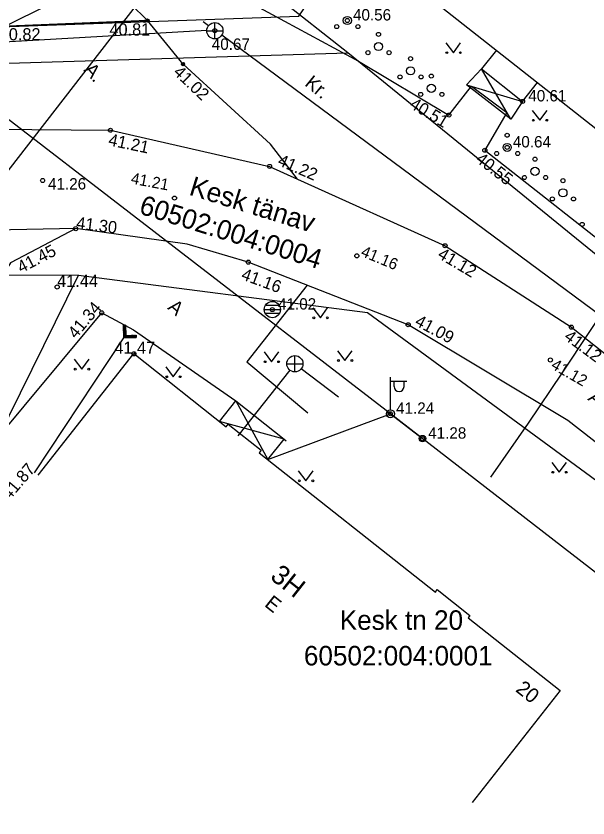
# Model space of a CAD drawing. Extents: x 641898 to 642452, y 6471715 to 6472255.
# Drawn here: x 641996.91 to 642032.09, y 6472036.05 to 6472085.4 of the extents above; entities that cross this region are included whole.
import ezdxf

# ---------------------------------------------------------------- set-up
doc = ezdxf.new("R2010")
doc.units = 0
for name, color, linetype in [('HALJASTUS', 7, 'Continuous'), ('HOONE', 7, 'Continuous'), ('HOONEDET', 7, 'Continuous'), ('KKAEV', 7, 'Continuous'), ('KORGUS-EH2000', 7, 'Continuous'), ('KTRASS', 7, 'Continuous'), ('MOOTMPUNKT', 7, 'Continuous'), ('MOOTPIIR', 7, 'Continuous'), ('MPOHULIIN', 7, 'Continuous'), ('PIIR', 7, 'Continuous'), ('POST', 7, 'Continuous'), ('PUU', 7, 'Continuous'), ('SITRASS', 7, 'Continuous'), ('SKKAEV', 7, 'Continuous'), ('TEE', 7, 'Continuous'), ('TRUUP', 7, 'Continuous')]:
    doc.layers.add(name, color=color, linetype=linetype)

msp = doc.modelspace()

# ---------------------------------------------------------------- linework, layer by layer
at = {"layer": 'HALJASTUS'}
for p, q in [((642023.35, 6472083.751), (642023.813, 6472083.144)), ((642023.813, 6472083.144), (642024.259, 6472083.751)), ((642028.664, 6472079.59), (642029.128, 6472078.983)), ((642029.128, 6472078.983), (642029.573, 6472079.59)), ((642015.168, 6472067.434), (642015.632, 6472066.828)), ((642015.632, 6472066.828), (642016.077, 6472067.434)), ((642012.169, 6472064.731), (642012.632, 6472064.124)), ((642012.632, 6472064.124), (642013.078, 6472064.731)), ((642016.68, 6472064.806), (642017.143, 6472064.2)), ((642017.143, 6472064.2), (642017.589, 6472064.806)), ((642000.495, 6472064.276), (642000.958, 6472063.669)), ((642000.958, 6472063.669), (642001.404, 6472064.276)), ((642006.121, 6472063.81), (642006.584, 6472063.204)), ((642006.584, 6472063.204), (642007.03, 6472063.81)), ((642029.864, 6472057.931), (642030.328, 6472057.324)), ((642030.328, 6472057.324), (642030.773, 6472057.931)), ((642014.275, 6472057.404), (642014.738, 6472056.798)), ((642014.738, 6472056.798), (642015.184, 6472057.404))]:
    msp.add_line(p, q, dxfattribs=at)
for centre in [(642023.412, 6472083.144), (642024.241, 6472083.144), (642028.727, 6472078.983), (642029.555, 6472078.983), (642015.231, 6472066.828), (642016.059, 6472066.828), (642012.231, 6472064.124), (642013.06, 6472064.124), (642016.742, 6472064.2), (642017.571, 6472064.2), (642000.557, 6472063.669), (642001.386, 6472063.669), (642006.183, 6472063.204), (642007.012, 6472063.204), (642029.927, 6472057.324), (642030.756, 6472057.324), (642014.337, 6472056.798), (642015.166, 6472056.798)]:
    msp.add_circle(centre, 0.055, dxfattribs=at)
at = {"layer": 'HOONE'}
for points in [[(642065.653, 6472064.719), (642027.624, 6472094.67), (642021.622, 6472087.119), (642059.651, 6472057.168), (642065.653, 6472064.719)], [(642026.461, 6472083.308), (642025.545, 6472082.144), (642028.07, 6472080.145), (642028.991, 6472081.315)], [(641998.282, 6472057.15), (642004.153, 6472064.63), (642009.847, 6472060.126), (642009.97, 6472060.281), (642011.991, 6472058.676), (642011.871, 6472058.525), (642022.707, 6472049.956), (642022.824, 6472050.104), (642024.833, 6472048.512), (642024.717, 6472048.366), (642030.388, 6472043.899), (642024.961, 6472037.001)]]:
    msp.add_lwpolyline(points, dxfattribs=at)
at = {"layer": 'HOONEDET'}
for p, q in [((642027.343, 6472079.046), (642025.545, 6472082.144)), ((642024.626, 6472081.165), (642028.07, 6472080.145)), ((642009.435, 6472060.453), (642010.441, 6472061.724)), ((642012.401, 6472058.107), (642013.398, 6472059.367))]:
    msp.add_line(p, q, dxfattribs=at)
for points in [[(642028.07, 6472080.145), (642027.343, 6472079.046), (642024.626, 6472081.165), (642025.545, 6472082.144)], [(642010.441, 6472061.724), (642013.398, 6472059.367)], [(642010.441, 6472061.724), (642012.401, 6472058.107)], [(642013.398, 6472059.367), (642009.435, 6472060.453)]]:
    msp.add_lwpolyline(points, dxfattribs=at)
at = {"layer": 'KKAEV'}
for p, q in [((642009.141, 6472083.993), (642009.141, 6472084.993)), ((642008.641, 6472084.493), (642009.641, 6472084.493)), ((642014.062, 6472063.5), (642014.062, 6472064.5)), ((642014.062, 6472063.5), (642014.062, 6472064.5)), ((642013.562, 6472064), (642014.562, 6472064)), ((642013.562, 6472064), (642014.562, 6472064))]:
    msp.add_line(p, q, dxfattribs=at)
for centre in [(642009.141, 6472084.493), (642014.062, 6472064), (642014.062, 6472064)]:
    msp.add_circle(centre, 0.5, dxfattribs=at)
at = {"layer": 'KORGUS-EH2000'}
for centre, radius in [((642004.997, 6472085.116), 0.1), ((642017.289, 6472085.124), 0.125), ((642009.141, 6472084.493), 0.125), ((642007.184, 6472082.444), 0.1), ((642028.07, 6472080.145), 0.125), ((642023.535, 6472079.305), 0.125), ((642002.72, 6472078.372), 0.125), ((642025.745, 6472077.14), 0.125), ((642027.12, 6472077.314), 0.125), ((642012.507, 6472076.145), 0.125), ((641998.548, 6472075.279), 0.125), ((642006.662, 6472074.194), 0.125), ((642000.586, 6472072.315), 0.125), ((642023.299, 6472071.264), 0.125), ((642011.197, 6472070.252), 0.125), ((642017.872, 6472070.641), 0.125), ((641999.443, 6472068.725), 0.125), ((642012.679, 6472067.335), 0.125), ((642002.184, 6472067.137), 0.125), ((642021.032, 6472066.402), 0.125), ((642031.072, 6472066.254), 0.125), ((642004.166, 6472064.613), 0.125), ((642029.779, 6472064.234), 0.125), ((642019.939, 6472060.923), 0.125), ((642021.913, 6472059.393), 0.125)]:
    msp.add_circle(centre, radius, dxfattribs=at)
at = {"layer": 'KTRASS'}
for points in [[(641991.013, 6472082.193), (642014.668, 6472093.944)], [(642008.421, 6472085.07), (642008.761, 6472084.818)], [(642008.642, 6472084.518), (641985.459, 6472083.184)], [(642044.143, 6472058.603), (642009.562, 6472084.224)], [(642013.751, 6472063.608), (642010.549, 6472059.572)], [(642016.739, 6472061.951), (642014.459, 6472063.696)]]:
    msp.add_lwpolyline(points, dxfattribs=at)
at = {"layer": 'MOOTMPUNKT'}
for centre in [(642004.815, 6472085.072), (642004.997, 6472085.116), (642007.184, 6472082.444), (642019.865, 6472060.944)]:
    msp.add_circle(centre, 0.075, dxfattribs=at)
at = {"layer": 'MOOTPIIR'}
msp.add_lwpolyline([(642014.306, 6472085.384), (642027.67, 6472104.979), (642055.501, 6472084.843), (642081.563, 6472094.262), (642123.938, 6472142.273), (642065.721, 6472244.475), (642008.922, 6472196.948), (642003.347, 6472200.453), (641979.65, 6472162.756), (641979.65, 6472162.756), (641986.045, 6472158.736), (642004.269, 6472142.365), (641987.048, 6472123.488), (641970.482, 6472097.889), (641986.758, 6472084.396)], close=True, dxfattribs=at)
at = {"layer": 'MPOHULIIN'}
for points in [[(642355.522, 6471813.313), (642331.534, 6471832.393), (642302.222, 6471855.921), (642271.629, 6471880.301), (642234.793, 6471909.555), (642198.436, 6471939.015), (642169.975, 6471961.956), (642133.076, 6471995.171), (642102.99, 6472021.089), (642074.552, 6472045.947), (642044.597, 6472041.824), (642019.939, 6472060.923), (641980.015, 6472091.706), (641945.513, 6472065.466), (641932.178, 6472056.628)], [(642012.401, 6472058.107), (642019.939, 6472060.923)]]:
    msp.add_lwpolyline(points, dxfattribs=at)
at = {"layer": 'PIIR'}
for p, q in [((642017.33, 6472083.13), (642002.45, 6472094.89)), ((641995.33, 6472082.47), (642017.33, 6472083.13)), ((642074.19, 6472036.84), (642017.33, 6472083.13)), ((642000.75, 6472069.46), (641989.88, 6472069.42)), ((641994.885, 6472057.561), (642000.75, 6472069.46)), ((642000.75, 6472069.46), (642018.53, 6472067.16)), ((642018.53, 6472067.16), (642037.8, 6472053))]:
    msp.add_line(p, q, dxfattribs=at)
at = {"layer": 'POST'}
for p, q in [((642019.939, 6472061.173), (642019.939, 6472063.173)), ((642019.939, 6472062.923), (642020.939, 6472062.923)), ((642020.166, 6472062.602), (642020.166, 6472062.923)), ((642020.778, 6472062.602), (642020.778, 6472062.923)), ((642019.939, 6472060.923), (642021.913, 6472059.393))]:
    msp.add_line(p, q, dxfattribs=at)
for centre, radius in [((642019.939, 6472060.923), 0.25), ((642021.913, 6472059.393), 0.2)]:
    msp.add_circle(centre, radius, dxfattribs=at)
msp.add_arc((642020.472, 6472062.602), 0.306, 180, 0, dxfattribs=at)
at = {"layer": 'PUU'}
for centre, radius in [((642017.289, 6472085.124), 0.25), ((642016.639, 6472084.749), 0.125), ((642017.939, 6472084.749), 0.125), ((642019.205, 6472084.27), 0.125), ((642019.205, 6472083.52), 0.25), ((642018.555, 6472083.145), 0.125), ((642019.855, 6472083.145), 0.125), ((642021.177, 6472082.774), 0.125), ((642021.177, 6472082.024), 0.25), ((642020.527, 6472081.649), 0.125), ((642021.827, 6472081.649), 0.125), ((642022.455, 6472081.702), 0.125), ((642022.455, 6472080.952), 0.25), ((642021.805, 6472080.577), 0.125), ((642023.105, 6472080.577), 0.125), ((642027.12, 6472078.064), 0.125), ((642027.12, 6472077.314), 0.25), ((642026.47, 6472076.939), 0.125), ((642027.77, 6472076.939), 0.125), ((642028.832, 6472076.59), 0.125), ((642028.832, 6472075.84), 0.25), ((642028.182, 6472075.465), 0.125), ((642029.482, 6472075.465), 0.125), ((642030.549, 6472075.267), 0.125), ((642030.549, 6472074.517), 0.25), ((642029.899, 6472074.142), 0.125), ((642031.199, 6472074.142), 0.125), ((642031.731, 6472072.576), 0.125)]:
    msp.add_circle(centre, radius, dxfattribs=at)
at = {"layer": 'SITRASS'}
for points in [[(642022.056, 6472087.662), (642011.704, 6472095.646), (641989.129, 6472066.508), (641984.461, 6472060.483)], [(642037.373, 6472074.688), (642033.85, 6472068.485), (642030.487, 6472063.43), (642028.405, 6472060.341), (642026.092, 6472057.029)]]:
    msp.add_lwpolyline(points, dxfattribs=at)
at = {"layer": 'SKKAEV'}
for p, q in [((642013.109, 6472067.585), (642012.249, 6472067.585)), ((642012.179, 6472067.335), (642013.179, 6472067.335)), ((642013.109, 6472067.085), (642012.249, 6472067.085))]:
    msp.add_line(p, q, dxfattribs=at)
msp.add_circle((642012.679, 6472067.335), 0.5, dxfattribs=at)
at = {"layer": 'TEE'}
for points in [[(641992.618, 6472094.578), (641991.404, 6472091.461), (641995.031, 6472087.196), (641995.679, 6472085.928), (641995.92, 6472084.762), (642004.997, 6472085.116), (642001.868, 6472088.221), (641999.18, 6472091.513), (641998.193, 6472092.499)], [(642003.242, 6472086.858), (642003.491, 6472086.884), (642008.621, 6472087.685), (642012.666, 6472085.497), (642017.972, 6472082.626), (642023.535, 6472079.305), (642024.936, 6472081.09), (642027.104, 6472079.457), (642025.745, 6472077.14), (642035.04, 6472069.842), (642036.698, 6472071.809), (642039.147, 6472069.927), (642037.552, 6472067.801), (642047.021, 6472060.414), (642048.68, 6472062.323), (642050.484, 6472060.969), (642049.417, 6472058.038), (642058.292, 6472050.781), (642057.815, 6472050.19)], [(642014.232, 6472075.365), (642012.567, 6472077.521), (642007.184, 6472082.444), (642004.997, 6472085.116), (641995.92, 6472084.762), (641995.551, 6472082.368), (641994.887, 6472081.189), (641991.484, 6472079.011), (641990.636, 6472078.487), (642002.72, 6472078.372), (642012.507, 6472076.145), (642014.232, 6472075.365)], [(641990.636, 6472078.487), (642002.72, 6472078.372), (642012.507, 6472076.145), (642014.232, 6472075.365), (642023.299, 6472071.264), (642031.072, 6472066.254), (642034.901, 6472063.222), (642037.522, 6472061.54), (642036.061, 6472059.791), (642034.51, 6472057.658), (642030.842, 6472060.508), (642021.032, 6472066.402), (642011.197, 6472070.252), (642007.439, 6472071.36), (642000.586, 6472072.315), (641991.524, 6472072.15)], [(642000.586, 6472072.315), (641996.568, 6472070.212), (641991.456, 6472061.912), (641989.327, 6472059.265)], [(642014.817, 6472068.835), (642011.099, 6472064.121), (642014.863, 6472060.978)], [(641994.371, 6472057.418), (641994.945, 6472058.469), (642002.184, 6472067.137), (642004.148, 6472066.081), (642010.441, 6472061.724)], [(642013.398, 6472059.367), (642013.535, 6472059.258)]]:
    msp.add_lwpolyline(points, dxfattribs=at)
at = {"layer": 'TRUUP'}
for p, q in [((642003.637, 6472066.373), (642003.495, 6472066.368)), ((642003.495, 6472066.368), (642003.524, 6472065.59)), ((642003.524, 6472066.369), (642003.497, 6472066.31)), ((642003.552, 6472066.37), (642003.499, 6472066.254)), ((642003.58, 6472066.371), (642003.501, 6472066.199)), ((642003.608, 6472066.372), (642003.503, 6472066.143)), ((642003.636, 6472066.373), (642003.505, 6472066.088)), ((642003.639, 6472066.32), (642003.507, 6472066.032)), ((642003.641, 6472066.264), (642003.509, 6472065.977)), ((642003.643, 6472066.209), (642003.511, 6472065.921)), ((642003.645, 6472066.153), (642003.513, 6472065.866)), ((642003.647, 6472066.098), (642003.515, 6472065.81)), ((642003.649, 6472066.042), (642003.517, 6472065.755)), ((642003.651, 6472065.987), (642003.52, 6472065.699)), ((642003.653, 6472065.931), (642003.522, 6472065.644)), ((642003.566, 6472066.371), (642003.592, 6472065.664)), ((642003.637, 6472066.373), (642003.661, 6472065.738)), ((642003.524, 6472065.59), (642004.301, 6472065.619)), ((642003.655, 6472065.876), (642003.525, 6472065.59)), ((642003.658, 6472065.82), (642003.553, 6472065.591)), ((642003.66, 6472065.765), (642003.581, 6472065.592)), ((642003.592, 6472065.664), (642004.299, 6472065.69)), ((642003.675, 6472065.738), (642003.609, 6472065.594)), ((642003.703, 6472065.739), (642003.637, 6472065.595)), ((642003.661, 6472065.738), (642004.296, 6472065.761)), ((642003.731, 6472065.74), (642003.665, 6472065.596)), ((642003.759, 6472065.742), (642003.693, 6472065.597)), ((642003.787, 6472065.743), (642003.721, 6472065.598)), ((642003.815, 6472065.744), (642003.748, 6472065.599)), ((642003.843, 6472065.745), (642003.776, 6472065.6)), ((642003.871, 6472065.746), (642003.804, 6472065.601)), ((642003.899, 6472065.747), (642003.832, 6472065.602)), ((642003.927, 6472065.748), (642003.86, 6472065.603)), ((642003.955, 6472065.749), (642003.888, 6472065.604)), ((642003.983, 6472065.75), (642003.916, 6472065.605)), ((642004.011, 6472065.751), (642003.944, 6472065.606)), ((642004.039, 6472065.752), (642003.972, 6472065.607)), ((642004.067, 6472065.753), (642004, 6472065.608)), ((642004.095, 6472065.754), (642004.028, 6472065.609)), ((642004.123, 6472065.755), (642004.056, 6472065.61)), ((642004.151, 6472065.756), (642004.084, 6472065.611)), ((642004.179, 6472065.757), (642004.112, 6472065.612)), ((642004.207, 6472065.758), (642004.14, 6472065.613)), ((642004.235, 6472065.759), (642004.168, 6472065.614)), ((642004.263, 6472065.76), (642004.196, 6472065.615)), ((642004.29, 6472065.761), (642004.224, 6472065.616)), ((642004.298, 6472065.717), (642004.252, 6472065.617)), ((642004.3, 6472065.661), (642004.28, 6472065.618)), ((642004.296, 6472065.761), (642004.301, 6472065.619))]:
    msp.add_line(p, q, dxfattribs=at)
msp.add_lwpolyline([(641998.056, 6472057.295), (642003.592, 6472065.664)], dxfattribs=at)

# ---------------------------------------------------------------- texts
at = {"layer": 'HOONE'}
for s, height, p in [('3H', 1.2, (642012.479, 6472050.802)), ('E', 0.9, (642012.14, 6472049.121)), ('20', 0.9, (642027.585, 6472043.878))]:
    msp.add_text(s, height=height, rotation=321.6478, dxfattribs=at).set_placement(p)
at = {"layer": 'KORGUS-EH2000'}
for s, height, p in [('40.56', 0.7, (642017.639, 6472085.124)), ('40.82', 0.75, (641995.91, 6472083.901)), ('40.81', 0.75, (642002.659, 6472084.197)), ('40.67', 0.7, (642008.954, 6472083.318)), ('40.61', 0.7, (642028.42, 6472080.145)), ('40.64', 0.7, (642027.47, 6472077.314)), ('41.26', 0.7, (641998.881, 6472074.723)), ('41.44', 0.75, (641999.443, 6472068.725)), ('41.02', 0.7, (642013.029, 6472067.335)), ('41.47', 0.75, (642002.959, 6472064.613)), ('41.24', 0.7, (642020.289, 6472060.923)), ('41.28', 0.7, (642022.263, 6472059.393))]:
    msp.add_text(s, height=height, dxfattribs=at).set_placement(p)
for s, height, rotation, p in [('41.02', 0.75, 316.3101, (642006.536, 6472081.88)), ('40.51', 0.75, 328.8414, (642021.066, 6472079.792)), ('41.21', 0.75, 348.2126, (642002.55, 6472077.449)), ('41.22', 0.75, 336.7318, (642012.948, 6472076.242)), ('40.55', 0.75, 321.9576, (642025.122, 6472076.485)), ('41.21', 0.7, 349.3741, (642003.939, 6472075.094)), ('41.30', 0.75, 352.8897, (642000.586, 6472072.315)), ('41.45', 0.75, 27.4277, (641997.228, 6472069.559)), ('41.16', 0.7, 337.4005, (642018.065, 6472070.65)), ('41.12', 0.75, 329.3028, (642022.786, 6472070.554)), ('41.16', 0.75, 339.6057, (642010.711, 6472069.215)), ('41.34', 0.75, 49.8977, (642000.599, 6472065.5)), ('41.09', 0.75, 331.8295, (642021.382, 6472066.402)), ('41.12', 0.75, 323.4547, (642030.566, 6472065.549)), ('41.12', 0.7, 330.1261, (642029.76, 6472063.747)), ('41.87', 0.75, 49.537, (641996.517, 6472055.573))]:
    msp.add_text(s, height=height, rotation=rotation, dxfattribs=at).set_placement(p)
at = {"layer": 'PIIR'}
for s, p in [('Kesk tänav', (642007.495, 6472074.414)), ('60502:004:0004', (642004.42, 6472073.258))]:
    msp.add_text(s, height=1.2, rotation=342.7807, dxfattribs=at).set_placement(p)
for s, p in [('Kesk tn 20', (642016.824, 6472047.629)), ('60502:004:0001', (642014.618, 6472045.439))]:
    msp.add_text(s, height=1.2, dxfattribs=at).set_placement(p)
at = {"layer": 'TEE'}
for s, rotation, p in [('A.', 311.8661, (642001.037, 6472082.056)), ('Kr.', 320.7542, (642014.619, 6472081.161)), ('A', 319.8025, (642006.189, 6472067.395)), ('A', 320.1408, (642032.032, 6472061.805))]:
    msp.add_text(s, height=0.85, rotation=rotation, dxfattribs=at).set_placement(p)

doc.saveas('drawing.dxf')
